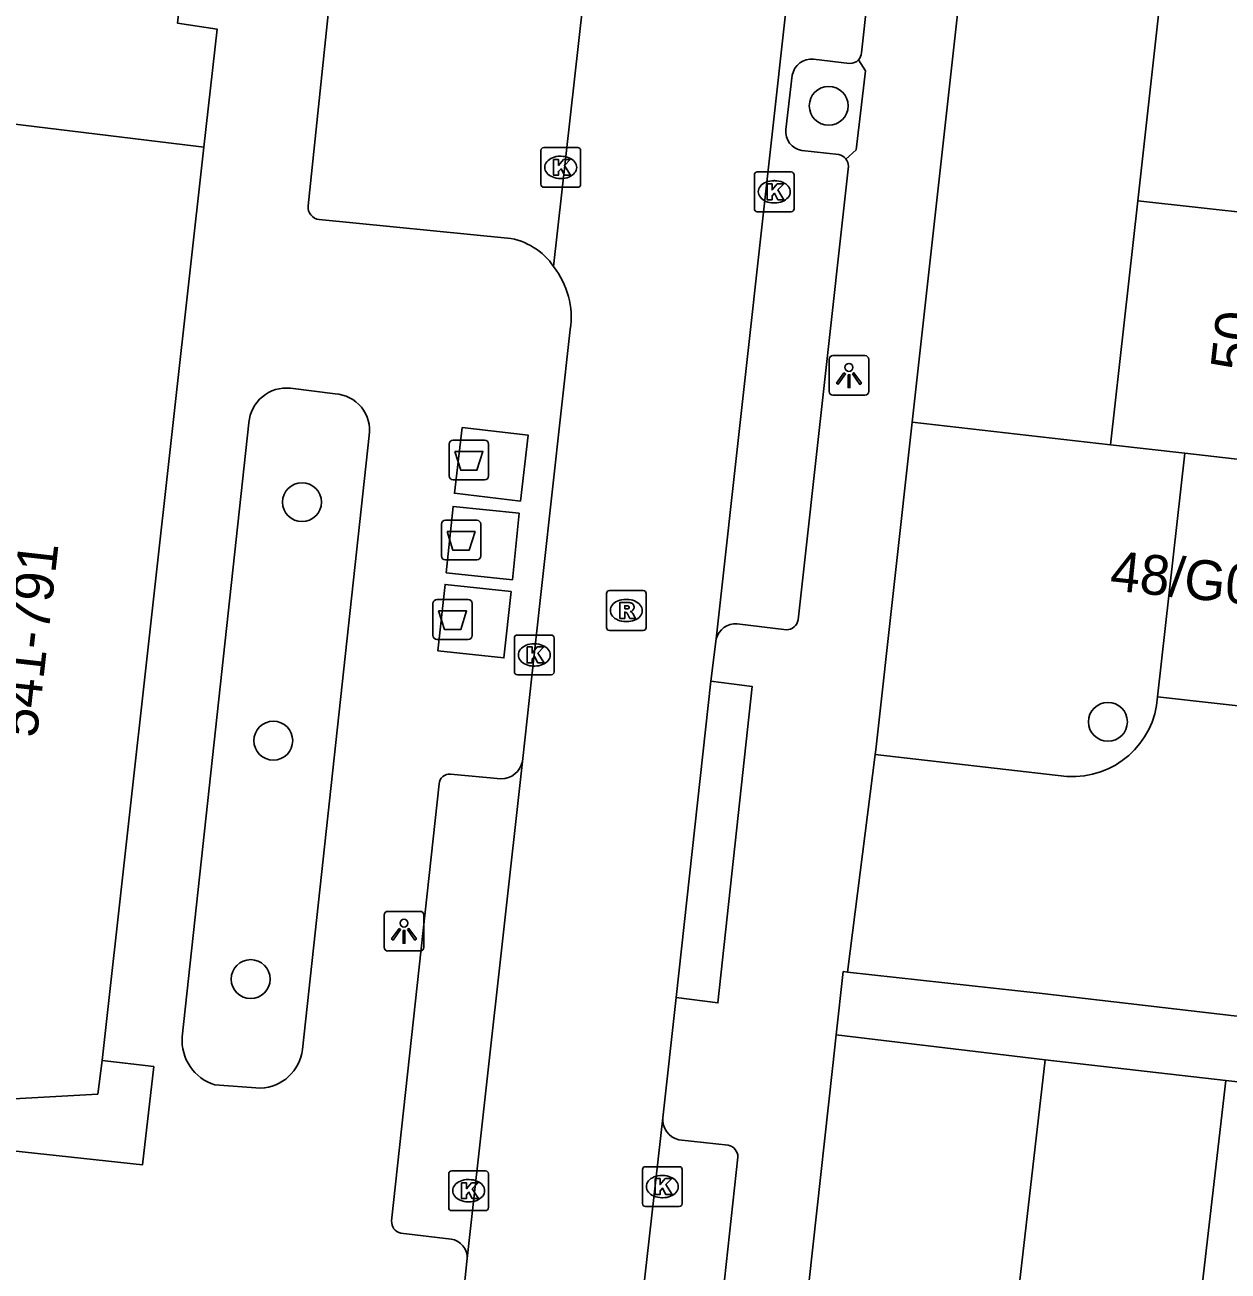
# Model space of a CAD drawing. Extents: x 161928 to 163055, y 386475 to 387428.
# Drawn here: x 162118.72 to 162148.97, y 387315.88 to 387347.19 of the extents above; entities that cross this region are included whole.
import ezdxf

# ---------------------------------------------------------------- set-up
doc = ezdxf.new("R2010")
doc.units = 0
for name, color, linetype in [('IMGEO_Afval_apart_plaats', 7, 'Continuous'), ('IMGEO_Boom', 7, 'Continuous'), ('IMGEO_Groenvoorziening', 7, 'Continuous'), ('IMGEO_Kolk', 7, 'Continuous'), ('IMGEO_Lichtpunt', 7, 'Continuous'), ('IMGEO_Pand', 7, 'Continuous'), ('IMGEO_Pand_nummerreeks', 7, 'Continuous'), ('IMGEO_Parkeervlak_open', 7, 'Continuous'), ('IMGEO_Rijbaan_lokaal_open', 7, 'Continuous'), ('IMGEO_Rioolput', 7, 'Continuous'), ('IMGEO_Voetpad_gesloten', 7, 'Continuous'), ('IMGEO_Voetpad_open', 7, 'Continuous')]:
    doc.layers.add(name, color=color, linetype=linetype)

msp = doc.modelspace()

# ---------------------------------------------------------------- linework, layer by layer
at = {"layer": 'IMGEO_Afval_apart_plaats'}
for p, q in [((162129.487, 387336.759), (162130.277, 387336.759)), ((162130.277, 387336.759), (162129.487, 387336.759)), ((162129.387, 387335.859), (162129.387, 387336.659)), ((162129.387, 387336.659), (162129.387, 387335.859)), ((162130.377, 387336.659), (162130.377, 387335.859)), ((162130.377, 387335.859), (162130.377, 387336.659)), ((162130.277, 387335.759), (162129.487, 387335.759)), ((162129.487, 387335.759), (162130.277, 387335.759)), ((162129.191, 387333.847), (162129.191, 387334.647)), ((162129.191, 387334.647), (162129.191, 387333.847)), ((162129.291, 387334.747), (162130.081, 387334.747)), ((162130.081, 387334.747), (162129.291, 387334.747)), ((162130.181, 387334.647), (162130.181, 387333.847)), ((162130.181, 387333.847), (162130.181, 387334.647)), ((162130.081, 387333.747), (162129.291, 387333.747)), ((162129.291, 387333.747), (162130.081, 387333.747)), ((162129.078, 387332.752), (162129.868, 387332.752)), ((162129.868, 387332.752), (162129.078, 387332.752)), ((162128.978, 387331.852), (162128.978, 387332.652)), ((162128.978, 387332.652), (162128.978, 387331.852)), ((162129.968, 387332.652), (162129.968, 387331.852)), ((162129.968, 387331.852), (162129.968, 387332.652)), ((162129.868, 387331.752), (162129.078, 387331.752)), ((162129.078, 387331.752), (162129.868, 387331.752))]:
    msp.add_line(p, q, dxfattribs=at)
for points in [[(162129.53, 387336.473), (162130.234, 387336.473), (162130.085, 387336.003), (162129.679, 387336.003), (162129.53, 387336.473)], [(162129.334, 387334.461), (162130.038, 387334.461), (162129.889, 387333.991), (162129.483, 387333.991), (162129.334, 387334.461)], [(162129.121, 387332.466), (162129.825, 387332.466), (162129.676, 387331.996), (162129.27, 387331.996), (162129.121, 387332.466)]]:
    msp.add_lwpolyline(points, dxfattribs=at)
for centre, start, end in [((162129.487, 387336.659), 90, 180), ((162129.487, 387336.659), 90, 180), ((162130.277, 387336.659), 0, 90), ((162130.277, 387336.659), 360, 90), ((162129.487, 387335.859), 180, 270), ((162129.487, 387335.859), 180, 270), ((162130.277, 387335.859), 270, 0), ((162130.277, 387335.859), 270, 0), ((162129.291, 387334.647), 90, 180), ((162129.291, 387334.647), 90, 180), ((162130.081, 387334.647), 0, 90), ((162130.081, 387334.647), 360, 90), ((162129.291, 387333.847), 180, 270), ((162129.291, 387333.847), 180, 270), ((162130.081, 387333.847), 270, 0), ((162130.081, 387333.847), 270, 0), ((162129.078, 387332.652), 90, 180), ((162129.078, 387332.652), 90, 180), ((162129.868, 387332.652), 0, 90), ((162129.868, 387332.652), 360, 90), ((162129.078, 387331.852), 180, 270), ((162129.078, 387331.852), 180, 270), ((162129.868, 387331.852), 270, 0), ((162129.868, 387331.852), 270, 0)]:
    msp.add_arc(centre, 0.1, start, end, dxfattribs=at)
at = {"layer": 'IMGEO_Boom'}
for centre in [(162138.928, 387345.159), (162125.688, 387335.2), (162145.946, 387329.68), (162124.965, 387329.207), (162124.397, 387323.214)]:
    msp.add_circle(centre, 0.489, dxfattribs=at)
at = {"layer": 'IMGEO_Groenvoorziening'}
msp.add_lwpolyline([(162141.026, 387337.206), (162146.014, 387336.642)], dxfattribs=at)
at = {"layer": 'IMGEO_Kolk'}
for p, q in [((162131.69, 387343.187), (162131.69, 387344.039)), ((162131.765, 387344.113), (162132.617, 387344.113)), ((162132.691, 387344.039), (162132.691, 387343.187)), ((162132.178, 387343.893), (162132.203, 387343.893)), ((162132.201, 387343.333), (162132.176, 387343.333)), ((162137.058, 387342.573), (162137.058, 387343.425)), ((162137.133, 387343.499), (162137.985, 387343.499)), ((162138.059, 387343.425), (162138.059, 387342.573)), ((162132.617, 387343.113), (162131.765, 387343.113)), ((162137.546, 387343.279), (162137.571, 387343.279)), ((162137.569, 387342.719), (162137.544, 387342.719)), ((162137.985, 387342.499), (162137.133, 387342.499)), ((162131.026, 387330.934), (162131.026, 387331.786)), ((162131.101, 387331.86), (162131.953, 387331.86)), ((162132.027, 387331.786), (162132.027, 387330.934)), ((162131.514, 387331.64), (162131.539, 387331.64)), ((162131.953, 387330.86), (162131.101, 387330.86)), ((162131.537, 387331.08), (162131.512, 387331.08)), ((162129.375, 387317.471), (162129.375, 387318.323)), ((162129.45, 387318.397), (162130.302, 387318.397)), ((162130.376, 387318.323), (162130.376, 387317.471)), ((162134.244, 387317.574), (162134.244, 387318.426)), ((162134.319, 387318.5), (162135.171, 387318.5)), ((162134.732, 387318.28), (162134.757, 387318.28)), ((162135.245, 387318.426), (162135.245, 387317.574)), ((162129.863, 387318.177), (162129.888, 387318.177)), ((162134.755, 387317.72), (162134.73, 387317.72)), ((162130.302, 387317.397), (162129.45, 387317.397)), ((162129.886, 387317.617), (162129.861, 387317.617)), ((162135.171, 387317.5), (162134.319, 387317.5))]:
    msp.add_line(p, q, dxfattribs=at)
for points in [[(162131.69, 387343.187), (162131.69, 387344.039)], [(162131.765, 387344.113), (162132.617, 387344.113)], [(162132.691, 387344.039), (162132.691, 387343.187)], [(162132.011, 387343.813), (162132.134, 387343.813), (162132.134, 387343.662), (162132.264, 387343.813), (162132.428, 387343.813), (162132.282, 387343.662), (162132.435, 387343.413), (162132.283, 387343.413), (162132.198, 387343.577), (162132.134, 387343.51), (162132.134, 387343.413), (162132.011, 387343.413), (162132.011, 387343.813)], [(162137.058, 387342.573), (162137.058, 387343.425)], [(162137.133, 387343.499), (162137.985, 387343.499)], [(162138.059, 387343.425), (162138.059, 387342.573)], [(162132.617, 387343.113), (162131.765, 387343.113)], [(162137.379, 387343.199), (162137.502, 387343.199), (162137.502, 387343.048), (162137.632, 387343.199), (162137.796, 387343.199), (162137.65, 387343.048), (162137.803, 387342.799), (162137.651, 387342.799), (162137.566, 387342.963), (162137.502, 387342.896), (162137.502, 387342.799), (162137.379, 387342.799), (162137.379, 387343.199)], [(162137.985, 387342.499), (162137.133, 387342.499)], [(162131.026, 387330.934), (162131.026, 387331.786)], [(162131.101, 387331.86), (162131.953, 387331.86)], [(162132.027, 387331.786), (162132.027, 387330.934)], [(162131.347, 387331.56), (162131.47, 387331.56), (162131.47, 387331.409), (162131.6, 387331.56), (162131.764, 387331.56), (162131.618, 387331.409), (162131.771, 387331.16), (162131.619, 387331.16), (162131.534, 387331.324), (162131.47, 387331.257), (162131.47, 387331.16), (162131.347, 387331.16), (162131.347, 387331.56)], [(162131.953, 387330.86), (162131.101, 387330.86)], [(162129.375, 387317.471), (162129.375, 387318.323)], [(162129.45, 387318.397), (162130.302, 387318.397)], [(162130.376, 387318.323), (162130.376, 387317.471)], [(162134.244, 387317.574), (162134.244, 387318.426)], [(162134.319, 387318.5), (162135.171, 387318.5)], [(162135.245, 387318.426), (162135.245, 387317.574)], [(162129.696, 387318.097), (162129.819, 387318.097), (162129.819, 387317.946), (162129.949, 387318.097), (162130.113, 387318.097), (162129.967, 387317.946), (162130.12, 387317.697), (162129.968, 387317.697), (162129.883, 387317.861), (162129.819, 387317.794), (162129.819, 387317.697), (162129.696, 387317.697), (162129.696, 387318.097)], [(162134.565, 387318.2), (162134.688, 387318.2), (162134.688, 387318.049), (162134.818, 387318.2), (162134.982, 387318.2), (162134.836, 387318.049), (162134.989, 387317.8), (162134.837, 387317.8), (162134.752, 387317.964), (162134.688, 387317.897), (162134.688, 387317.8), (162134.565, 387317.8), (162134.565, 387318.2)], [(162130.302, 387317.397), (162129.45, 387317.397)], [(162135.171, 387317.5), (162134.319, 387317.5)]]:
    msp.add_lwpolyline(points, dxfattribs=at)
for centre, start, end in [((162131.767, 387344.037), 91.552, 178.448), ((162131.767, 387344.037), 91.552, 178.448), ((162132.615, 387344.037), 1.552, 88.448), ((162132.615, 387344.037), 1.552, 88.448), ((162137.135, 387343.423), 91.552, 178.448), ((162137.135, 387343.423), 91.552, 178.448), ((162137.983, 387343.423), 1.552, 88.448), ((162137.983, 387343.423), 1.552, 88.448), ((162131.767, 387343.189), 181.552, 268.448), ((162131.767, 387343.189), 181.552, 268.448), ((162132.615, 387343.189), 271.552, 358.448), ((162132.615, 387343.189), 271.552, 358.448), ((162137.135, 387342.575), 181.552, 268.448), ((162137.135, 387342.575), 181.552, 268.448), ((162137.983, 387342.575), 271.552, 358.448), ((162137.983, 387342.575), 271.552, 358.448), ((162131.103, 387331.784), 91.552, 178.448), ((162131.103, 387331.784), 91.552, 178.448), ((162131.951, 387331.784), 1.552, 88.448), ((162131.951, 387331.784), 1.552, 88.448), ((162131.103, 387330.936), 181.552, 268.448), ((162131.103, 387330.936), 181.552, 268.448), ((162131.951, 387330.936), 271.552, 358.448), ((162131.951, 387330.936), 271.552, 358.448), ((162129.452, 387318.321), 91.552, 178.448), ((162129.452, 387318.321), 91.552, 178.448), ((162130.3, 387318.321), 1.552, 88.448), ((162130.3, 387318.321), 1.552, 88.448), ((162134.321, 387318.424), 91.552, 178.448), ((162134.321, 387318.424), 91.552, 178.448), ((162135.169, 387318.424), 1.552, 88.448), ((162135.169, 387318.424), 1.552, 88.448), ((162129.452, 387317.473), 181.552, 268.448), ((162129.452, 387317.473), 181.552, 268.448), ((162130.3, 387317.473), 271.552, 358.448), ((162130.3, 387317.473), 271.552, 358.448), ((162134.321, 387317.576), 181.552, 268.448), ((162134.321, 387317.576), 181.552, 268.448), ((162135.169, 387317.576), 271.552, 358.448), ((162135.169, 387317.576), 271.552, 358.448)]:
    msp.add_arc(centre, 0.0765, start, end, dxfattribs=at)
for centre, major_axis, ratio, start_param, end_param in [((162132.177, 387343.613), (-0.387, 0.002), 0.722429, 4.712389, 7.853982), ((162132.202, 387343.613), (-0.39, 0.002), 0.717154, 1.570796, 4.712389), ((162137.545, 387342.999), (-0.387, 0.002), 0.722429, 4.712389, 7.853982), ((162137.57, 387342.999), (-0.39, 0.002), 0.717154, 1.570796, 4.712389), ((162131.513, 387331.36), (-0.387, 0.002), 0.722429, 4.712389, 7.853982), ((162131.538, 387331.36), (-0.39, 0.002), 0.717154, 1.570796, 4.712389), ((162134.731, 387318), (-0.387, 0.002), 0.722429, 4.712389, 7.853982), ((162134.756, 387318), (-0.39, 0.002), 0.717154, 1.570796, 4.712389), ((162129.862, 387317.897), (-0.387, 0.002), 0.722429, 4.712389, 7.853982), ((162129.887, 387317.897), (-0.39, 0.002), 0.717154, 1.570796, 4.712389)]:
    msp.add_ellipse(centre, major_axis=major_axis, ratio=ratio, start_param=start_param, end_param=end_param, dxfattribs=at)
at = {"layer": 'IMGEO_Lichtpunt'}
for p, q in [((162138.937, 387338.787), (162138.937, 387337.98)), ((162138.937, 387338.787), (162138.937, 387337.98)), ((162139.839, 387338.882), (162139.031, 387338.882)), ((162139.839, 387338.882), (162139.031, 387338.882)), ((162139.933, 387337.98), (162139.933, 387338.787)), ((162139.933, 387337.98), (162139.933, 387338.787)), ((162139.031, 387337.886), (162139.839, 387337.886)), ((162139.031, 387337.886), (162139.839, 387337.886)), ((162128.654, 387324.917), (162127.846, 387324.917)), ((162128.654, 387324.917), (162127.846, 387324.917)), ((162127.752, 387324.822), (162127.752, 387324.015)), ((162127.752, 387324.822), (162127.752, 387324.015)), ((162128.748, 387324.015), (162128.748, 387324.822)), ((162128.748, 387324.015), (162128.748, 387324.822)), ((162127.846, 387323.921), (162128.654, 387323.921)), ((162127.846, 387323.921), (162128.654, 387323.921))]:
    msp.add_line(p, q, dxfattribs=at)
for points in [[(162139.311, 387338.451), (162139.35, 387338.423), (162139.162, 387338.161), (162139.124, 387338.188), (162139.311, 387338.451)], [(162139.413, 387338.403), (162139.46, 387338.403), (162139.46, 387338.081), (162139.413, 387338.081), (162139.413, 387338.403)], [(162139.523, 387338.423), (162139.561, 387338.45), (162139.748, 387338.188), (162139.709, 387338.16), (162139.523, 387338.423)], [(162128.126, 387324.486), (162128.165, 387324.458), (162127.977, 387324.196), (162127.939, 387324.223), (162128.126, 387324.486)], [(162128.228, 387324.438), (162128.275, 387324.438), (162128.275, 387324.116), (162128.228, 387324.116), (162128.228, 387324.438)], [(162128.338, 387324.458), (162128.376, 387324.485), (162128.563, 387324.223), (162128.524, 387324.195), (162128.338, 387324.458)]]:
    msp.add_lwpolyline(points, dxfattribs=at)
for centre in [(162139.436, 387338.585), (162128.251, 387324.62)]:
    msp.add_circle(centre, 0.0994, dxfattribs=at)
for centre, start, end in [((162139.031, 387338.787), 90, 180), ((162139.031, 387338.787), 90, 180), ((162139.839, 387338.787), 0, 90), ((162139.839, 387338.787), 0, 90), ((162139.031, 387337.98), 180, 270), ((162139.031, 387337.98), 180, 270), ((162139.839, 387337.98), 270, 0), ((162139.839, 387337.98), 270, 360), ((162127.846, 387324.822), 90, 180), ((162127.846, 387324.822), 90, 180), ((162128.654, 387324.822), 0, 90), ((162128.654, 387324.822), 0, 90), ((162127.846, 387324.015), 180, 270), ((162127.846, 387324.015), 180, 270), ((162128.654, 387324.015), 270, 0), ((162128.654, 387324.015), 270, 360)]:
    msp.add_arc(centre, 0.0946, start, end, dxfattribs=at)
at = {"layer": 'IMGEO_Pand'}
for points in [[(162146.695, 387342.776), (162147.356, 387348.739)], [(162116.743, 387344.905), (162123.02, 387344.143), (162123.222, 387344.118)], [(162123.222, 387344.118), (162122.486, 387337.503), (162120.667, 387321.165)], [(162146.014, 387336.642), (162146.695, 387342.776)], [(162154.28, 387341.934), (162146.695, 387342.776)], [(162147.876, 387336.435), (162146.014, 387336.642)], [(162147.195, 387330.304), (162147.876, 387336.435)], [(162150.872, 387336.091), (162147.876, 387336.435)], [(162150.192, 387329.971), (162147.195, 387330.304)], [(162114.218, 387319.971), (162120.555, 387320.323), (162120.667, 387321.165)], [(162143.245, 387311.421), (162144.372, 387321.189)], [(162148.907, 387320.667), (162144.372, 387321.189)], [(162147.309, 387306.81), (162148.907, 387320.667)]]:
    msp.add_lwpolyline(points, dxfattribs=at)
at = {"layer": 'IMGEO_Parkeervlak_open'}
for points in [[(162138.547, 387346.329), (162139.452, 387346.223)], [(162137.846, 387344.568), (162138.012, 387345.932)], [(162139.185, 387343.933), (162138.251, 387344.036)]]:
    msp.add_lwpolyline(points, dxfattribs=at)
for centre, radius, start, end in [((162138.492, 387345.845), 0.487, 83.4757, 169.6793), ((162139.465, 387346.511), 0.288, 267.4435, 317.9754), ((162138.342, 387344.525), 0.498, 175.0622, 259.5002), ((162139.117, 387343.631), 0.31, 38.3516, 77.3438)]:
    msp.add_arc(centre, radius, start, end, dxfattribs=at)
at = {"layer": 'IMGEO_Rijbaan_lokaal_open'}
for points in [[(162132.012, 387341.118), (162138.235, 387396.651)], [(162143.165, 387395.601), (162139.246, 387360.16), (162136.099, 387331.767)], [(162131.227, 387328.684), (162131.527, 387331.36), (162132.431, 387339.539)], [(162136.099, 387331.767), (162135.964, 387330.704)], [(162135.964, 387330.704), (162135.097, 387322.754)], [(162129.842, 387316.193), (162131.227, 387328.684)], [(162139.402, 387323.39), (162140.096, 387328.858)], [(162144.917, 387328.306), (162140.096, 387328.858)], [(162139.402, 387323.39), (162144.289, 387322.85), (162164.32, 387320.52), (162165.179, 387328.308)], [(162135.097, 387322.754), (162134.759, 387319.727)], [(162134.759, 387319.727), (162133.97, 387312.761)], [(162129.74, 387315.226), (162129.833, 387316.114), (162129.842, 387316.193)]]:
    msp.add_lwpolyline(points, dxfattribs=at)
for centre, radius, start, end in [((162130.384, 387339.841), 2.069, 351.6089, 38.1138), ((162145.056, 387330.445), 2.143, 266.2752, 356.2318)]:
    msp.add_arc(centre, radius, start, end, dxfattribs=at)
at = {"layer": 'IMGEO_Rioolput'}
for p, q in [((162133.414, 387332.977), (162134.266, 387332.977)), ((162133.339, 387332.051), (162133.339, 387332.903)), ((162133.827, 387332.757), (162133.852, 387332.757)), ((162134.34, 387332.903), (162134.34, 387332.051)), ((162133.85, 387332.197), (162133.825, 387332.197)), ((162134.266, 387331.977), (162133.414, 387331.977))]:
    msp.add_line(p, q, dxfattribs=at)
for points in [[(162133.414, 387332.977), (162134.266, 387332.977)], [(162133.339, 387332.051), (162133.339, 387332.903)], [(162133.928, 387332.675), (162133.676, 387332.677), (162133.676, 387332.277)], [(162134.34, 387332.903), (162134.34, 387332.051)], [(162133.676, 387332.277), (162133.8, 387332.277), (162133.8, 387332.439), (162133.811, 387332.439)], [(162133.854, 387332.596), (162133.8, 387332.596), (162133.8, 387332.515)], [(162133.8, 387332.515), (162133.852, 387332.515)], [(162133.858, 387332.41), (162133.929, 387332.277), (162134.069, 387332.277), (162134.004, 387332.403)], [(162134.266, 387331.977), (162133.414, 387331.977)]]:
    msp.add_lwpolyline(points, dxfattribs=at)
for centre, radius, start, end in [((162133.416, 387332.901), 0.0765, 91.552, 178.448), ((162133.416, 387332.901), 0.0765, 91.552, 178.448), ((162134.264, 387332.901), 0.0765, 1.552, 88.448), ((162134.264, 387332.901), 0.0765, 1.552, 88.448), ((162133.927, 387332.565), 0.109, 350.3612, 89.416), ((162133.81, 387332.386), 0.0533, 26.0293, 88.6989), ((162133.836, 387332.704), 0.19, 274.7715, 282.9687), ((162133.86, 387332.5), 0.0964, 77.0061, 93.1865), ((162133.874, 387332.557), 0.0378, 276.6634, 79.6772), ((162133.925, 387332.565), 0.112, 277.5842, 350.9817), ((162133.909, 387332.35), 0.108, 29.5134, 73.7905), ((162133.416, 387332.053), 0.0765, 181.552, 268.448), ((162133.416, 387332.053), 0.0765, 181.552, 268.448), ((162134.264, 387332.053), 0.0765, 271.552, 358.448), ((162134.264, 387332.053), 0.0765, 271.552, 358.448)]:
    msp.add_arc(centre, radius, start, end, dxfattribs=at)
for centre, major_axis, ratio, start_param, end_param in [((162133.826, 387332.477), (-0.387, 0.002), 0.722429, 4.712389, 7.853982), ((162133.851, 387332.477), (-0.39, 0.002), 0.717154, 1.570796, 4.712389)]:
    msp.add_ellipse(centre, major_axis=major_axis, ratio=ratio, start_param=start_param, end_param=end_param, dxfattribs=at)
at = {"layer": 'IMGEO_Voetpad_gesloten'}
for points in [[(162129.716, 387337.078), (162131.374, 387336.88), (162131.176, 387335.227), (162129.518, 387335.425), (162129.716, 387337.078)], [(162131.148, 387334.921), (162130.976, 387333.252), (162129.315, 387333.424), (162129.487, 387335.092), (162131.148, 387334.921)], [(162130.944, 387332.954), (162130.764, 387331.285), (162129.104, 387331.464), (162129.284, 387333.133), (162130.944, 387332.954)]]:
    msp.add_lwpolyline(points, dxfattribs=at)
at = {"layer": 'IMGEO_Voetpad_open'}
for points in [[(162128.351, 387398.751), (162127.574, 387391.838), (162122.559, 387347.235), (162123.553, 387347.09), (162123.222, 387344.118)], [(162147.797, 387398.11), (162141.026, 387337.206)], [(162141.005, 387357.879), (162139.75, 387346.488)], [(162125.84, 387342.645), (162126.777, 387351.64)], [(162139.679, 387346.318), (162139.852, 387346.038), (162139.615, 387344.056), (162139.36, 387343.823)], [(162139.423, 387343.641), (162138.159, 387332.246)], [(162130.853, 387341.837), (162126.117, 387342.3)], [(162125.395, 387338.062), (162126.52, 387337.919)], [(162122.675, 387321.766), (162124.355, 387337.197)], [(162140.096, 387328.858), (162140.111, 387328.977), (162141.026, 387337.206)], [(162127.374, 387336.872), (162125.696, 387321.449)], [(162137.864, 387331.992), (162136.626, 387332.143)], [(162135.964, 387330.704), (162137.007, 387330.566), (162136.141, 387322.614), (162135.097, 387322.754)], [(162129.421, 387328.364), (162130.689, 387328.244)], [(162127.941, 387317.14), (162129.137, 387328.121)], [(162139.114, 387321.811), (162139.294, 387323.402), (162139.402, 387323.39)], [(162138.032, 387311.991), (162139.019, 387320.966), (162139.114, 387321.811)], [(162144.372, 387321.189), (162139.114, 387321.811)], [(162120.667, 387321.165), (162121.962, 387321.014), (162121.679, 387318.551), (162114.141, 387319.358)], [(162124.644, 387320.473), (162123.499, 387320.554)], [(162148.907, 387320.667), (162153.394, 387320.161)], [(162135.159, 387319.179), (162136.396, 387319.042)], [(162136.646, 387318.741), (162136.059, 387313.341)], [(162129.438, 387316.68), (162128.172, 387316.831)]]:
    msp.add_lwpolyline(points, dxfattribs=at)
for centre, radius, start, end in [((162139.472, 387346.504), 0.278, 317.9967, 356.6679), ((162139.113, 387343.636), 0.31, 0.9939, 37.1931), ((162126.165, 387342.622), 0.326, 175.9921, 261.5298), ((162130.639, 387340.199), 1.652, 33.81, 82.5622), ((162125.293, 387337.127), 0.941, 83.7924, 175.7103), ((162126.475, 387337.011), 0.91, 351.2371, 87.1687), ((162136.586, 387331.642), 0.502, 85.3746, 165.639), ((162137.859, 387332.296), 0.305, 270.9978, 350.4602), ((162130.682, 387328.802), 0.558, 270.7385, 347.8171), ((162129.392, 387328.11), 0.256, 83.573, 177.5298), ((162123.847, 387321.676), 1.175, 175.6248, 252.7962), ((162124.604, 387321.571), 1.099, 272.1015, 353.6062), ((162135.28, 387319.687), 0.523, 175.6513, 256.6021), ((162136.34, 387318.741), 0.306, 0.0277, 79.396), ((162128.236, 387317.12), 0.296, 176.1255, 257.4361), ((162129.364, 387316.207), 0.479, 358.2979, 81.0582)]:
    msp.add_arc(centre, radius, start, end, dxfattribs=at)

# ---------------------------------------------------------------- texts
at = {"layer": 'IMGEO_Pand_nummerreeks'}
for s, rotation, p in [('50', 83.6674, (162149.516, 387338.461)), ('541-791', 83.6048, (162119.021, 387329.257)), ('48/G06', 354.0531, (162145.972, 387332.989))]:
    msp.add_text(s, height=1, rotation=rotation, dxfattribs=at).set_placement(p)

doc.saveas('drawing.dxf')
